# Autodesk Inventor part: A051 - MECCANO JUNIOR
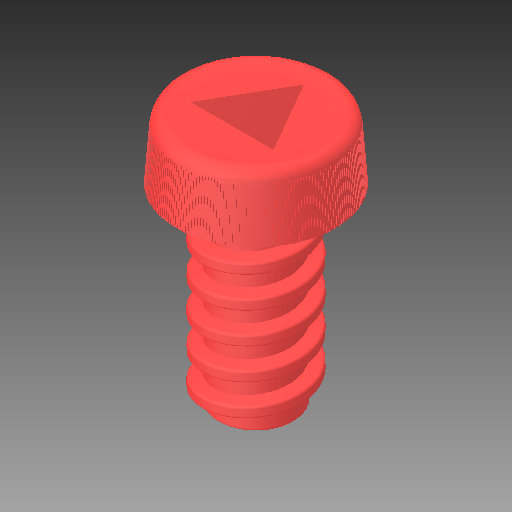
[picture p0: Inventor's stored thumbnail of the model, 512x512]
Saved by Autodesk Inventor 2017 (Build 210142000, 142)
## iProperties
Created: 2016-10
Part Number: A051 - MECCANO JUNIOR
Material: solidworks materials|PVC rigide
Document SubType Name: Modeling
Designer: ficho
Density: 1.3 g/cm^3
Appearance: 255,20,20
Mass: 2.11434 g
Surface Area: 17.5926 cm^2
Volume: 1.62642 cm^3
Sending System: SolidWorks 2013
Last Author: lucie-nico
Last Saved: 2016-10-25
Author: ficho
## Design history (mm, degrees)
feature "Répétition circulaire1"
node "Solide1"
